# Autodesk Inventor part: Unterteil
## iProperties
Created: 2007-04
Part Number: Unterteil
Material: Aluminium - 6061
Document SubType Name: Sheet Metal
Designer: Benno
Manufacturer: Standard
Standards Organization: Custom
Author: Benno
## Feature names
1. Bohrung1 [Hole]
2. Extrusion1
3. Bohrung2 [Hole]
4. Grobblech1
5. Grobblech2
6. Biegung1
7. Grobblech3
8. Biegung2
9. ExtrusionAbwicklung1
